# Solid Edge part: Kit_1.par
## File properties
Sűrűség: 0,000 kg/m^3
Pontosság: 0,990
Author: bmolnar
Last saved by: bmolnar
Revision: 77
Username: bmolnar
Dokumentum tartalom típus: 0
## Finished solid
Body 1: solid body, 40 faces, 57 edges, 47 vertices.
  Faces by surface: cylinder 14, plane 13, cone 9, torus 4
  Edges by curve: circle 43, line 14
Bounding box of the edges (mm; curved faces can reach further): 35.700 x 35.525 x 4.050, from (-17.85, -16.85, 75.05) to (17.85, 18.675, 79.1).
Cylindrical faces by radius (mm): R1.25 x2, R2.5 x4, R6.27 x1, R6.85 x1, R8.16 x1, R8.25 x1, R11.5 x1, R15.375 x1, R16.85 x1, R17.85 x1
Conical faces (half-angle, radius in mm at the cone's reference point): 3 deg R8.205 x1, 7 deg R7.5925 x1, 14 deg R6.135 x1, 14 deg R6.4811 x1, 17 deg R6.135 x1, 23 deg R6.829 x1, 45 deg R7.1 x1, 45 deg R11.15 x1, 87 deg R6.1765 x1
Toroidal faces (ring radius, tube radius in mm): R6.8057 r0.2025 x1, R7.2522 r0.2925 x1, R7.96 r0.2 x1, R11.9 r0.4 x1
Planar faces by outward normal: +z 6, -z 5, oblique 2
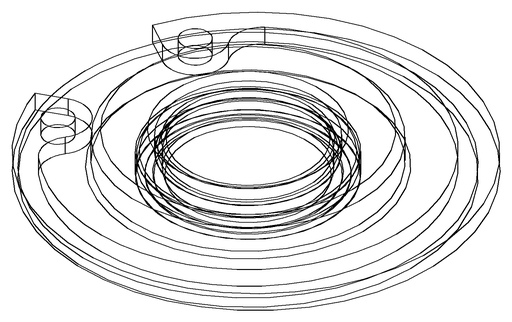
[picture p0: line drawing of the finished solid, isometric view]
